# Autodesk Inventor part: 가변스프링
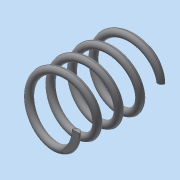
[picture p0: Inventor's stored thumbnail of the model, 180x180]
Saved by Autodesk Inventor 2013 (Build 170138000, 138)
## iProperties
Created: 2015-09
Part Number: 가변스프링
Material: 일반
Document SubType Name: Modeling
Designer: dgall
Density: 1 g/cm^3
Mass: 0.357755 g
Surface Area: 7.43542 cm^2
Volume: 0.357755 cm^3
Author: dgall
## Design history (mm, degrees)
sketch "스케치1"
  geometry: L1 (0, 0)-(8, 0); L2 (0, 0)-(0, 42); L3 (0, 42)-(8, 42); C1 r 1 at (8, 0)
  constraints: 6 end point, 2 perpendicular, 1 centre point, 1 coincident, 1 horizontal, 1 vertical alignment
  dimensions: "d0" = 16 diameter of L1.end L2; "d2" = 42 distance between parallel lines of L3 L1 (derived); "d3" = 2 diameter of C1
feature "코일1" pitch "d4" = 10; turns "d6" = 4; dims "d5" = 42 (= d2), "d7" = 0, angle "d8" = 90 deg, angle "d9" = 90 deg, "d10" = 0, "d11" = 0
feature "분할1"
node "작업 평면1"
feature "분할2"
node "솔리드1"
other parameters: "d12" = 24
